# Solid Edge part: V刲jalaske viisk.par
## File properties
Author: KULL
Template: Iso Metric Part.par
Last saved by: KULL
Revision: 4
Application: Solid Edge
Accuracy: 0,990
Face Style: Model Default
Fill Style: Normal
Coef. of Thermal Exp: 0.0
Thermal Conductivity: 0.0
Specific Heat: 0.0
Modulus of Elasticity: 0.0
Poisson's Ratio: 0.0
Yield Stress: 0.0
Ultimate Stress: 0.0
Elongation: 0.0
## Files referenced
..\..\Mootor\Mootor_ASM_1.asm
lG:\Haapsalu Kolledz\Solid edge leong\Solid edge Sync practice\ROVER_Heiko_Kull_EKSAM\Mootor\Mootor_ASM_1.asm
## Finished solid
Body 1: solid body, 38 faces, 76 edges, 36 vertices.
  Faces by surface: cylinder 12, plane 10, torus 6, swept 5, spline 4, blend 1
  Edges by curve: circle 30, line 30, spline 10, intersection 6
Body 2: sheet body, 1 face, 17 edges, 12 vertices.
  Faces by surface: plane 1
  Edges by curve: circle 6, line 6, intersection 5
Bounding box of the edges (mm; curved faces can reach further): 92.734 x 15.191 x 44.481, from (-46.367, 30.4866, 4.8428) to (46.367, 45.6778, 49.3236).
Cylindrical faces by radius (mm): R0.4 x6, R3 x2, R5 x4
Toroidal faces (ring radius, tube radius in mm): R2.6 r0.4 x2, R4.6 r0.4 x4
Planar faces by outward normal: oblique 10
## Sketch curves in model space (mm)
line (36.0001, 41.2522, 42.2653) -> (-36, 41.2522, 42.2653)
closed spline through (-1.9994, 41.2531, 42.2663), (0.121, 39.9661, 40.7326), (1.9848, 41.408, 42.451), (-0.3592, 42.5198, 43.776)
closed spline through (32.8006, 41.253, 42.2662), (36.1935, 39.1962, 39.815), (39.1757, 41.5009, 42.5617), (35.4244, 43.2785, 44.6801)
closed spline through (14.8006, 41.253, 42.2662), (18.1935, 39.1962, 39.815), (21.1757, 41.5009, 42.5617), (17.4244, 43.2785, 44.6801)
closed spline through (-21.1994, 41.253, 42.2662), (-17.8065, 39.1962, 39.815), (-14.8243, 41.5009, 42.5617), (-18.5756, 43.2785, 44.6801)
closed spline through (-39.1994, 41.253, 42.2662), (-35.8065, 39.1962, 39.815), (-32.8243, 41.5009, 42.5617), (-36.5756, 43.2785, 44.6801)
closed spline through (34.0006, 41.2531, 42.2663), (36.121, 39.9661, 40.7326), (37.9848, 41.408, 42.451), (35.6408, 42.5198, 43.776)
closed spline through (16.0006, 41.2531, 42.2663), (18.121, 39.9661, 40.7326), (19.9848, 41.408, 42.451), (17.6408, 42.5198, 43.776)
closed spline through (-19.9994, 41.2531, 42.2663), (-17.879, 39.9661, 40.7326), (-16.0152, 41.408, 42.451), (-18.3592, 42.5198, 43.776)
closed spline through (-37.9994, 41.2531, 42.2663), (-35.879, 39.9661, 40.7326), (-34.0152, 41.408, 42.451), (-36.3592, 42.5198, 43.776)
closed spline through (-3.1994, 41.253, 42.2662), (0.1935, 39.1962, 39.815), (3.1757, 41.5009, 42.5617), (-0.5756, 43.2785, 44.6801)
closed spline through (-1.9994, 37.4228, 45.4802), (0.121, 36.1359, 43.9465), (1.9848, 37.5778, 45.6649), (-0.3592, 38.6896, 46.9899)
arc centre (-36, 37.4339, 45.4934) radius 5 from (-40, 35.5055, 43.1953) through (-38.2361, 34.5592, 42.0676) to (-36, 34.2199, 41.6632)
line (-40, 35.5055, 43.1953) -> (-43.367, 35.5055, 43.1953)
arc centre (-43.367, 37.4339, 45.4934) radius 3 from (-43.367, 39.3622, 47.7915) through (-46.3657, 37.3767, 45.4253) to (-43.367, 35.5055, 43.1953)
line (-40, 39.3622, 47.7915) -> (-43.367, 39.3622, 47.7915)
arc centre (-36, 37.4339, 45.4934) radius 5 from (-36, 40.6478, 49.3236) through (-38.2361, 40.3085, 48.9193) to (-40, 39.3622, 47.7915)
line (36, 40.6478, 49.3236) -> (-36, 40.6478, 49.3236)
arc centre (36, 37.4339, 45.4934) radius 5 from (40, 39.3622, 47.7915) through (38.2361, 40.3085, 48.9193) to (36, 40.6478, 49.3236)
line (43.367, 39.3622, 47.7915) -> (40, 39.3622, 47.7915)
arc centre (43.367, 37.4339, 45.4934) radius 3 from (43.367, 35.5055, 43.1953) through (46.3657, 37.491, 45.5615) to (43.367, 39.3622, 47.7915)
line (43.367, 35.5055, 43.1953) -> (40, 35.5055, 43.1953)
arc centre (36, 37.4339, 45.4934) radius 5 from (36, 34.2199, 41.6632) through (38.2361, 34.5592, 42.0676) to (40, 35.5055, 43.1953)
line (36, 34.2199, 41.6632) -> (-36, 34.2199, 41.6632)
closed spline through (34.0006, 37.4228, 45.4802), (36.121, 36.1359, 43.9465), (37.9848, 37.5778, 45.6649), (35.6408, 38.6896, 46.9899)
closed spline through (16.0006, 37.4228, 45.4802), (18.121, 36.1359, 43.9465), (19.9848, 37.5778, 45.6649), (17.6408, 38.6896, 46.9899)
closed spline through (-19.9994, 37.4228, 45.4802), (-17.879, 36.1359, 43.9465), (-16.0152, 37.5778, 45.6649), (-18.3592, 38.6896, 46.9899)
closed spline through (-37.9994, 37.4228, 45.4802), (-35.879, 36.1359, 43.9465), (-34.0152, 37.5778, 45.6649), (-36.3592, 38.6896, 46.9899)
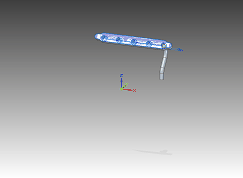
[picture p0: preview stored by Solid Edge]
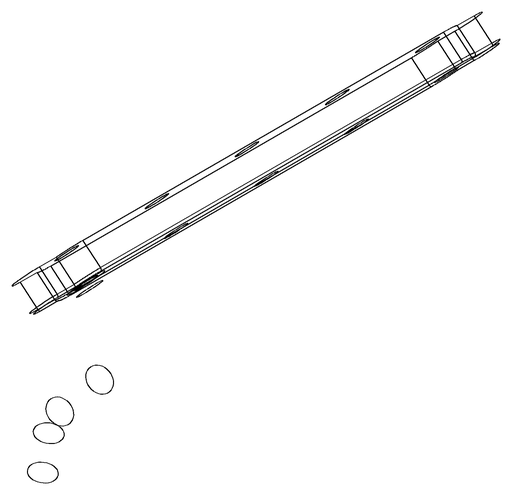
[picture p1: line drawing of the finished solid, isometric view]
